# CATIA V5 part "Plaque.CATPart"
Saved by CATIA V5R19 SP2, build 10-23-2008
Part number: Plaque
Bounding box of the stored display mesh (mm): x 0 to 40, y -80 to 80, z -250 to 250
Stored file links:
  D:\SCHOOL\FRANCE\BANC_POUTRE_EN_MOUSSE\Plaque.CATPart
  C:\Program Files\Dassault Systemes\B19\intel_a\reffiles\standard\MetricThickPitch.txt
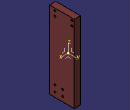
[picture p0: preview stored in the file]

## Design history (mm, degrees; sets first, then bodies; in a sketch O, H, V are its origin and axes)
AxisSystem1: origin (0, 0, 0), X (1, 0, 0), Y (0, 1, 0), Z (0, 0, 1)
Body1 (main body)
  Sketch1 on YZ plane of AxisSystem1, origin (0, 0, 0), H (0, 1, 0), V (0, 0, 1)
    line L1 (80, 250) -> (80, -250)
    line L2 (80, -250) -> (-80, -250)
    line L3 (-80, -250) -> (-80, 250)
    line L4 (-80, 250) -> (80, 250)
    distance L1 V = 80
    distance L4 H = 250
    vertical: L1 V, L3 V
    horizontal: L2 H, L4 H
    equidistance: L1 L3 O, L2 L4 O
  Pad1: profile Sketch1, direction (1, 0, 0), length 40
  Sketch2 on start face of Pad1, origin (0, 11.4929, 141.0763), H (0, 1, 0), V (0, 0, -1)
    point P1 (53.5071, -93.9237)
    reference projected line E1 (68.5071, 341.0763) -> (68.5071, -58.9237) from edge [start face of Pad1 | face of Pad1 from Sketch1.L1]
    reference projected line E2 (68.5071, -108.9237) -> (-91.4929, -108.9237) from edge [start face of Pad1 | face of Pad1 from Sketch1.L4]
    distance E1 P1 = 15
    distance P1 E2 = 15
  Hole1: placed by Sketch2, at (0, 65, 235) direction (1, 0, 0), diameter 12, through (limit type 6), counterbore diameter 18, counterbore depth 5
  RectPattern1: of Hole1, direction 1 instances 2, spacing 30, along edge [start face of Pad1 | face of Pad1 from Sketch1.L1] reversed, direction 2 instances 2, spacing 110, along edge [start face of Pad1 | face of Pad1 from Sketch1.L4]
  Sketch3 on start face of Pad1, origin (0, 40.9137, -172.2286), H (0, 1, 0), V (0, 0, -1)
    point P1 (-35.9137, 47.7714)
    reference projected line E1 (-120.9137, 77.7714) -> (39.0863, 77.7714) from edge [start face of Pad1 | face of Pad1 from Sketch1.L2]
    reference projected line E2 (39.0863, 27.7714) -> (39.0863, -372.2286) from edge [start face of Pad1 | face of Pad1 from Sketch1.L1]
    distance E1 P1 = 30
    distance E2 P1 = 75
  Hole2: placed by Sketch3, at (0, 5, -220) direction (1, 0, 0), diameter 12, through (limit type 6), counterbore diameter 18, counterbore depth 5
  RectPattern2: of Hole2, direction 1 instances 2, spacing 40, along edge [start face of Pad1 | face of Pad1 from Sketch1.L1], direction 2 instances 2, spacing 50, along edge [start face of Pad1 | face of Pad1 from Sketch1.L2] reversed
